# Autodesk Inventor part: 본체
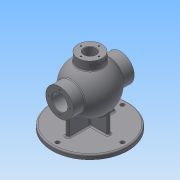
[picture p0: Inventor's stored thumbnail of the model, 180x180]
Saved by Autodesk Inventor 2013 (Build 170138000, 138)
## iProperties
Created: 2020-08
Part Number: 본체
Material: Generic
Document SubType Name: Modeling
Designer: user
Density: 1 g/cm^3
Author: user
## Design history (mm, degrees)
revolve "회전1" stored, may be unused: angle "d10" = 90 deg
node "작업 평면1"
sketch "스케치2"
  geometry: C1 r 85 at (0, 0); 1 further point
  constraints: 1 centre point, 1 coincident
  dimensions: "d12" = 170 diameter of C1
extrude "돌출1" join sketch "스케치2" distance "d13" = 10; taper "d14" = 0 deg
sketch "스케치3"
  geometry: C1 r 85 at (0, 0) reference; 4 further points
  constraints: 1 vertical alignment, 5 other
  dimensions: "d15" = 72.5 distance of point (0, 72.5) C1.centre; "d18" = 360 deg dimension on C1.centre point (0, 72.5) (derived)
hole "구멍1" sketch "스케치3" at (0, 72.5), (-72.5, 0), (0, -72.5), (72.5, 0) diameter "d20" = 9; stored, may be unused: countersink angle "d24" = 90 deg, drill point angle "d26" = 118 deg; dims "d21" = 6, "d22" = 4, "d23" = 2, "d25" = 8
sketch "스케치4"
  geometry: L1 (4, -52)-(-4, -52); L2 (-4, -52)-(-4, 52); L3 (-4, 52)-(4, 52); L4 (4, 52)-(4, -52); L5 (4, -52)-(-4, 52); L6 (-4, -52)-(4, 52); L7 (-43, 4)-(43, 4); L8 (43, 4)-(43, -4); L9 (43, -4)-(-43, -4); L10 (-43, -4)-(-43, 4); L11 (-43, 4)-(43, -4); L12 (43, 4)-(-43, -4); C1 r 85 at (0, 0) reference
  constraints: 24 end point, 4 midpoint, 4 parallel, 2 horizontal, 2 perpendicular
  dimensions: "d27" = 104 distance of L3.end L1.start; "d29" = 8 distance of L2.end L3.end; "d30" = 86 distance of L8.end L9.end; "d31" = 8 distance of L9.end L7.start
extrude "돌출2" join sketch "스케치4" stored distance "d32" = 10; taper "d33" = 0 deg
sketch "스케치5"
  geometry: C1 r 31 at (0, 0) reference; 4 further points
  constraints: 1 vertical alignment, 5 other
  dimensions: "d34" = 24 distance of point (0, 24) C1.centre; "d37" = 360 deg dimension on C1.centre point (0, 24) (derived)
hole "구멍2" sketch "스케치5" at (0, 24), (-24, 0), (0, -24), (24, 0) diameter "d39" = 3.242; stored, may be unused: countersink angle "d43" = 90 deg, drill point angle "d45" = 118 deg; dims "d40" = 12, "d41" = 4, "d42" = 2, "d44" = 15
node "작업 평면2"
sketch "스케치6"
  geometry: C1 r 27 at (0, 0); 1 further point
  constraints: 1 centre point, 1 coincident
  dimensions: "d47" = 54 diameter of C1
extrude "돌출3" join sketch "스케치6" stored distance "d48" = 10; taper "d49" = 0 deg
sketch "스케치7"
  geometry: C1 r 27 at (0, 0) reference; C2 r 13 at (0, 0)
  constraints: 1 centre point, 1 coincident
  dimensions: "d50" = 26 diameter of C2
extrude "돌출4" cut sketch "스케치7" stored distance "d51" = 10; taper "d52" = 0 deg
sketch "스케치8"
  geometry: C1 r 13 at (0, 0) reference; 4 further points
  constraints: 1 vertical alignment, 5 other
  dimensions: "d53" = 20 distance of C1.centre point (0, 20); "d56" = 360 deg dimension on C1.centre point (0, 20) (derived)
hole "구멍3" sketch "스케치8" at (0, 20), (-20, 0), (0, -20), (20, 0) diameter "d58" = 3.242; stored, may be unused: countersink angle "d62" = 90 deg, drill point angle "d64" = 118 deg; dims "d59" = 12, "d60" = 4, "d61" = 2, "d63" = 15
chamfer "모따기1" distance "d65" = 1; stored, may be unused: second distance "d66" = 2, angle "d67" = 45 deg
fillet "모깎기1" dims "d68" = 3
fillet "모깎기2" dims "d69" = 3
fillet "모깎기3" dims "d70" = 3
node "작업 평면3"
node "작업 평면4"
node "작업 평면5"
sketch "스케치11"
  geometry: L1 (0, 27)-(-17.714, 27) reference; L2 (0, 27)-(0, -27) reference; 2 further points
  constraints: 1 other
  dimensions: "d82" = 9 distance from line of point (-9, 0) L2; "d83" = 27 distance from line of point (-9, 0) L1
feature "엠보싱3" sketch "스케치11" dims "d0" = 136, "d2" = 106, "d3" = 86, "d5" = 62, "d6" = 35, "d18" = 360 deg (derived), "d79" = 37, "d80" = 16, "d81" = 1.75, "d84" = 0.5, "d85" = 0
chamfer "모따기2" distance "d86" = 1; stored, may be unused: second distance "d87" = 2, angle "d88" = 45 deg
node "솔리드1"
mirror "대칭1"
sketch "스케치1"
  geometry: L1 (0, 68)-(0, -68); L2 (0, 68)-(31, 68); L3 (31, -68)-(0, -68); L4 (31, 42.988)-(31, 68); L5 (31, -68)-(31, -42.988); L6 (17.5, 68)-(17.5, 52); L7 (17.5, 68)-(17.5, 39.278); L8 (17.5, -52)-(18.5, -52); L9 (18.5, -52)-(18.5, -50.25); L10 (18.5, -50.25)-(17.5, -50.25); L11 (17.5, -39.278)-(17.5, -50.25); L12 (17.5, -52)-(17.5, -68); A1 r 53 centre (0, 0) between (31, -42.988) and (31, 42.988); A2 r 43 centre (0, 0) between (17.5, -39.278) and (17.5, 39.278); 2 further points
  constraints: 24 end point, 7 collinear, 6 perpendicular, 4 point on circle, 3 coincident, 3 parallel, 2 centre point, 2 point on line, 1 midpoint, 1 vertical
  dimensions: "d0" = 136 distance of L1.start L1.end; "d2" = 106 diameter of A1; "d3" = 86 diameter of A2; "d5" = 62 diameter of L4 L1; "d6" = 35 diameter of L6 L1; "d79" = 37 diameter of L9 L1; "d80" = 16 distance of L8.start L12.end; "d81" = 1.75 distance of L8.end L9.end
other parameters: "d4" = 62, "d11" = -85, "d46" = 65
